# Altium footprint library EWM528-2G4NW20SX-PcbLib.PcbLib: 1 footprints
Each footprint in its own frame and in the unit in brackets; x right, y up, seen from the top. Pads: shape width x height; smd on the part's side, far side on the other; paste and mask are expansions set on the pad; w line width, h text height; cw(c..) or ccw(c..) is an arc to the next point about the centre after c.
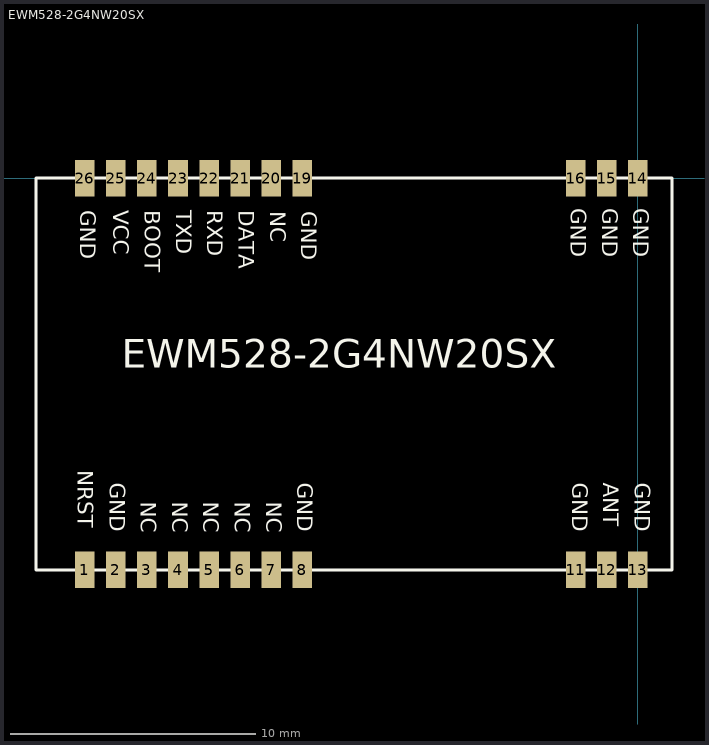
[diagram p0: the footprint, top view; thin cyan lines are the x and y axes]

## EWM528-2G4NW20SX [mm] "26mm**16mm*3.23mm-S"
pads (22):
  rect 0.8x1.5 smd: 1(-22.6,-16) 2(-21.33,-16) 3(-20.06,-16) 4(-18.79,-16) 5(-17.52,-16) 6(-16.25,-16) 7(-14.98,-16) 8(-13.71,-16) 11(-2.54,-16) 12(-1.27,-16) 13(0,-16) 14(0,0) 15(-1.27,0) 16(-2.54,0) 19(-13.71,0) 20(-14.98,0) 21(-16.25,0) 22(-17.52,0) 23(-18.79,0) 24(-20.06,0) 25(-21.33,0) 26(-22.6,0)
Top Overlay:
  lines w0.127: -24.6,-16 -24.6,0 1.4,0 1.4,-16 -24.6,-16
  text "GND" at -0.408,-1.224 h1.1
  text "EWM528-2G4NW20SX" at -21.082,-8.128 h2
  text "NC" at -15.257,-1.351 h1.1
  text "DATA" at -16.536,-1.301 h1.1
  text "RXD" at -17.814,-1.301 h1.1
  text "TXD" at -19.093,-1.301 h1.1
  text "BOOT" at -20.372,-1.301 h1.1
  text "VCC" at -21.651,-1.301 h1.1
  text "GND" at -23.01,-1.301 h1.1
  text "GND" at -13.97,-1.351 h1.1
  text "NRST" at -23.114,-11.938 h1.1
  text "GND" at -21.811,-12.441 h1.1
  text "NC" at -20.532,-13.214 h1.1
  text "NC" at -19.253,-13.214 h1.1
  text "NC" at -17.974,-13.214 h1.1
  text "NC" at -16.696,-13.214 h1.1
  text "NC" at -15.417,-13.214 h1.1
  text "GND" at -14.138,-12.441 h1.1
  text "GND" at -0.358,-12.441 h1.1
  text "ANT" at -1.637,-12.441 h1.1
  text "GND" at -2.916,-12.441 h1.1
  text "GND" at -2.966,-1.224 h1.1
  text "GND" at -1.687,-1.224 h1.1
